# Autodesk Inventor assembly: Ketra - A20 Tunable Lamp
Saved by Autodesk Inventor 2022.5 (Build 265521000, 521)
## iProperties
Created: 2025-02
Part Number: Ketra - A20 Tunable Lamp
Document SubType Name: Assembly
Designer: AdminForWorker
Title: Ketra - A20 Tunable Lamp v4
Author: AdminForWorker
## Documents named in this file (2)
- c:\worker\convert-fusion-r06-cosv3\tmp\job-1\154\temp\files\f1c30072-313d-4739-8c53-79efa0d23b5e\Ketra - A20 Tunable Lamp v4.iam
- c:\worker\convert-fusion-r06-cosv3\tmp\job-1\154\temp\files\f1c30072-313d-4739-8c53-79efa0d23b5e\Ketra A20.ipt
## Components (1 placed, 1 different names)
1. Ketra A20:1
